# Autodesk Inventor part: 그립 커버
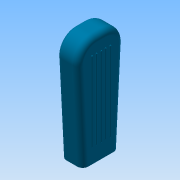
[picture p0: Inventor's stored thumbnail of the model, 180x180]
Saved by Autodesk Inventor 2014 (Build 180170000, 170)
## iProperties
Created: 2017-10
Part Number: 그립 커버
Material: 고무
Document SubType Name: Modeling
Designer: mduedu
Density: 0.93 g/cm^3
Mass: 10.5883 g
Surface Area: 64.0587 cm^2
Volume: 11.3852 cm^3
Appearance: 하늘색 중간
Author: mduedu
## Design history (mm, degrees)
sketch "스케치1"
  geometry: L1 (0, 7.5)-(50, 7.5); L2 (50, 7.5)-(50, -7.5); L3 (50, -7.5)-(0, -7.5); L4 (0, 10)-(49.477, 12.593); L5 (60, 2.607)-(60, 0); L6 (0, 0)-(60, 0); L7 (60, -2.607)-(60, 0); L8 (0, -10)-(49.477, -12.593); L9 (0, 10)-(0, -10); A1 r 10 centre (50, 2.607) between (60, 2.607) and (49.477, 12.593); A2 r 10 centre (50, -2.607) between (49.477, -12.593) and (60, -2.607); 2 further points
  constraints: 18 end point, 4 point on circle, 4 symmetric about line, 3 point on line, 2 centre point, 2 midpoint, 2 parallel, 2 perpendicular, 2 tangent, 1 coincident, 1 horizontal, 1 other
  dimensions: "d2" = 15 distance of L1.end L2.end; "d3" = 10 radius of A1; "d5" = 10 distance from line of L4.start L6; "d7" = 50 distance between parallel lines of L9 L2; "d8" = 10 distance between parallel lines of L7 L2; "d9" = 93 deg angle of L4 L9
extrude "돌출1" new body sketch "스케치1" stored distance "d10" = 12; taper "d11" = 0 deg
extrude "돌출2" cut sketch "스케치1" stored distance "d12" = 6; taper "d13" = 0 deg
fillet "모깎기1"
fillet "모깎기2" dims "d14" = 0.5
fillet "모깎기3" dims "d15" = 3
sketch "스케치2"
  geometry: L1 (0, 8)-(0, 52); L2 (-6.996, 0)-(6.996, 0) reference; L3 (-2.607, 57)-(2.607, 57) reference; L4 (0, 52)-(-0.5, 52); L5 (-0.5, 52)-(-0.5, 8); L6 (-0.5, 8)-(0, 8); L7 (0, 8)-(0, 52); 2 further points
  constraints: 10 end point, 2 parallel, 1 horizontal, 1 midpoint, 1 perpendicular, 1 vertical, 1 vertical alignment
  dimensions: "d16" = 8 distance from line of L1.start L2; "d17" = 5 distance from line of L1.end L3; "d18" = 0.5 distance of L1.end L4.end
revolve "회전1" sketch "스케치2" stored, may be unused: angle "d19" = 90 deg
fillet "모깎기4" dims "d20" = 0.5
chamfer "모따기1" distance "d27" = 0.5; stored, may be unused: second distance "d28" = 2, angle "d29" = 45 deg
node "솔리드1"
pattern_linear "직사각형 패턴1" dims "d23" = 5, "d26" = -5
mirror "대칭1"
